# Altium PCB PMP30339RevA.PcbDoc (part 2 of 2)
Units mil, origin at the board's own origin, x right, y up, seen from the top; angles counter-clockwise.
Board outline 3000 x 2600 mil, 4 copper layers (Top Layer, Signal Layer 1, Signal Layer 2, Bottom Layer), stack 61.2 mil thick; 113 components, 43 nets, 222 pads, 187 vias.
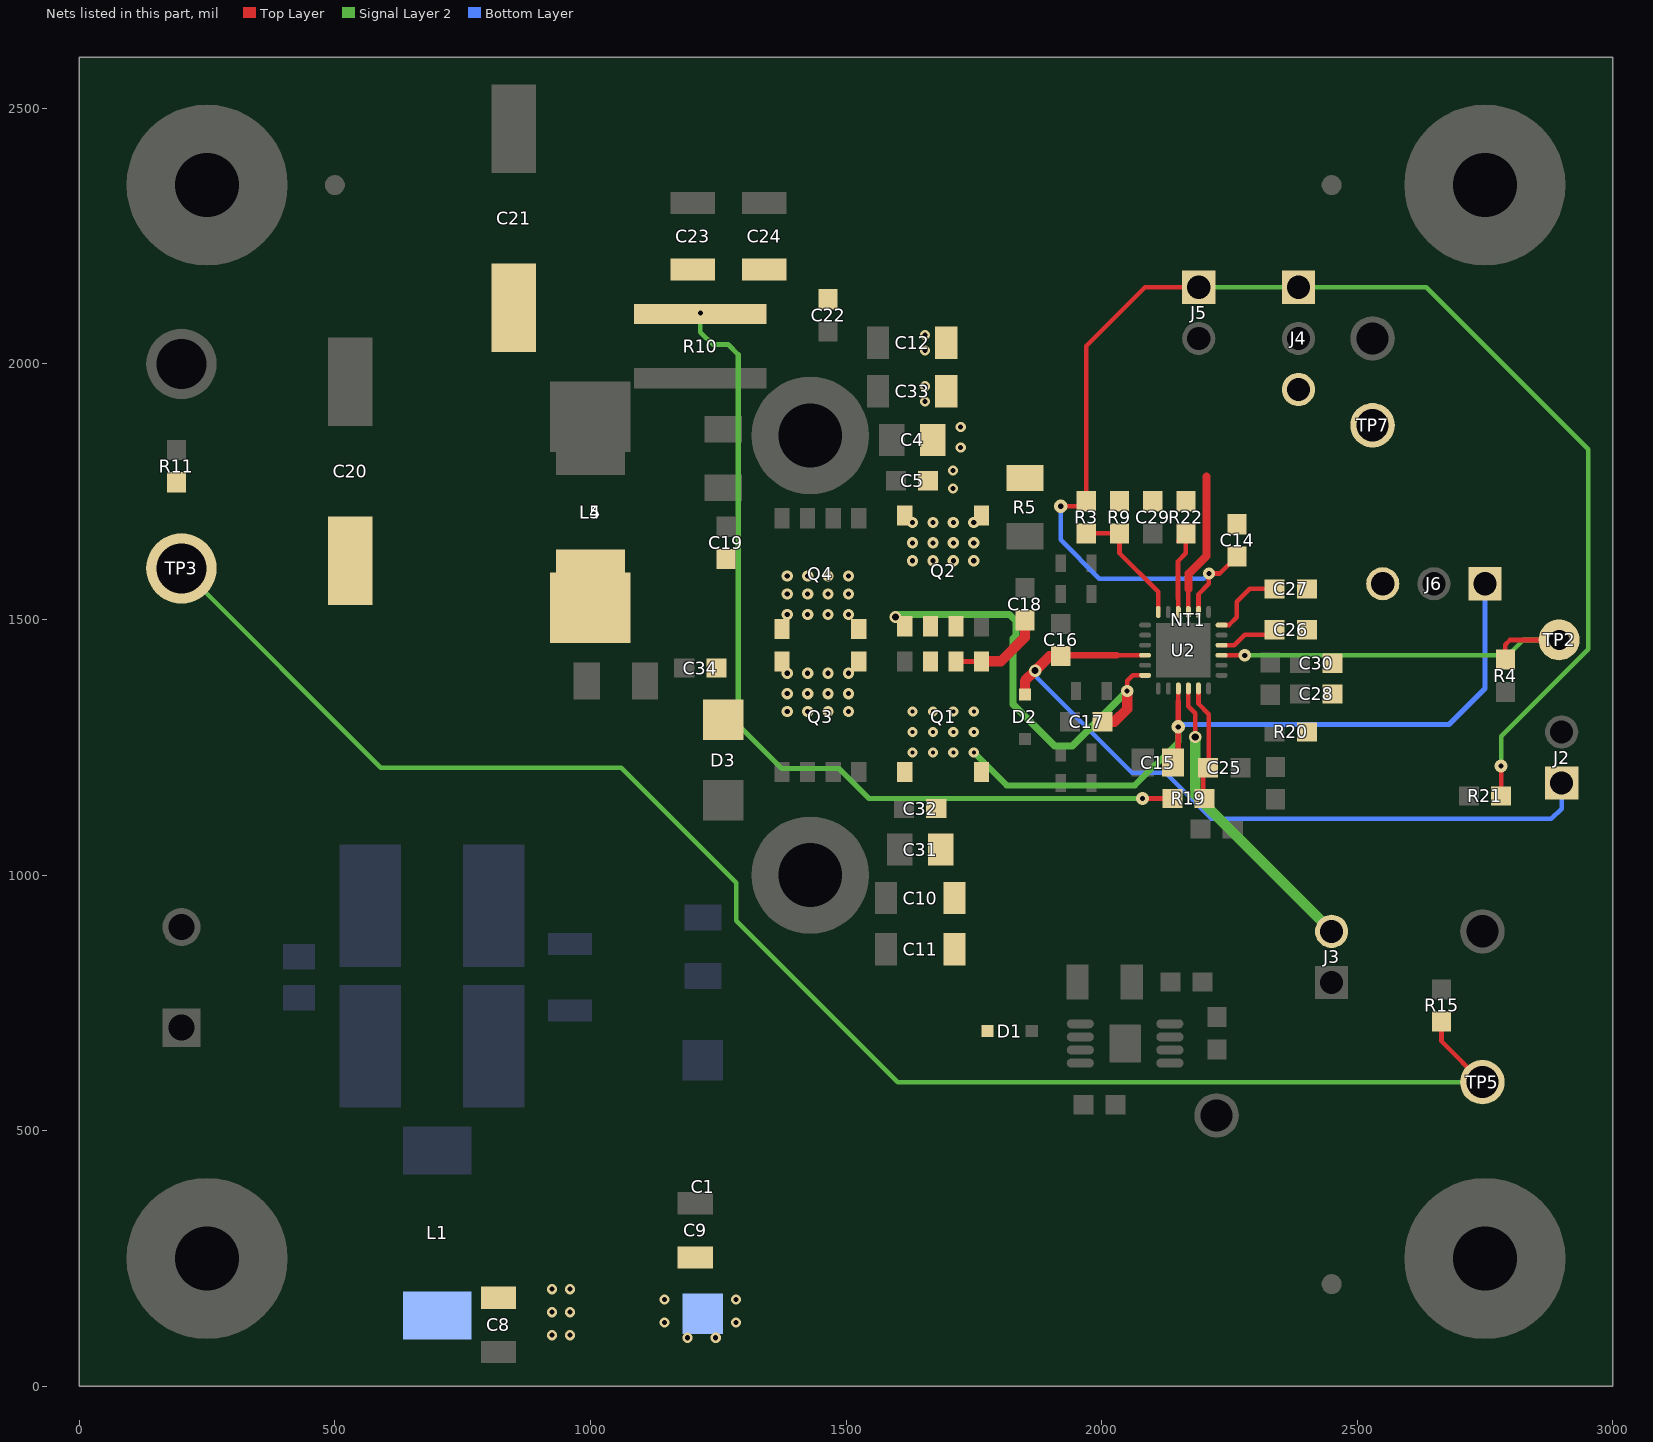
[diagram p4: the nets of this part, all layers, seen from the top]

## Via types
v1: diameter 20, hole 10, Top Layer to Bottom Layer, tented both sides, 54 vias
v2: diameter 20, hole 10, Top Layer to Bottom Layer, 49 vias
v3: diameter 22, hole 10, Top Layer to Bottom Layer, 36 vias
v4: diameter 20, hole 8, Top Layer to Bottom Layer, 12 vias
v5: diameter 18, hole 8, Top Layer to Bottom Layer, 10 vias
v6: diameter 24, hole 10, Top Layer to Bottom Layer, tented both sides, 7 vias
v7: diameter 26, hole 10, Top Layer to Bottom Layer, tented both sides, 6 vias
v8: diameter 24, hole 14, Top Layer to Bottom Layer, 5 vias
v9: diameter 26, hole 10, Top Layer to Bottom Layer, 4 vias
v10: diameter 24, hole 14, Top Layer to Bottom Layer, tented both sides, 2 vias
v11: diameter 30, hole 20, Top Layer to Bottom Layer, 1 vias
v12: diameter 22, hole 10, Top Layer to Bottom Layer, tented both sides, 1 vias

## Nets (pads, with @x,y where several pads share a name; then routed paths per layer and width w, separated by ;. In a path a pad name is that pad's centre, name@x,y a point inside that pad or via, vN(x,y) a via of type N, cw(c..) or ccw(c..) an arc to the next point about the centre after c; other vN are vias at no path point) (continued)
OSC: R3.2 R9.1 U2.6 | length 250.1
  Top Layer w9: R3.2@1970,1668.5 R9.1@2035,1668.5 2035,1630 2110.79,1554.21 U2.6@2110.79,1514.8
PG: R4.2 TP2.1 U2.21 | length 815.8
  Top Layer w9: U2.21@2234.8,1430.16 2269.84,1430.16 2270,1430 v6(2280,1430) ; R4.2@2790,1421.5 2790,1451.02 2798.98,1460 TP2.1@2895,1460
  Signal Layer 2 w9: v6(2280,1430) 2795,1430 2825,1460 TP2.1@2895,1460 ; TP2.1@2895.01,1430.11 TP2.1@2899.82,1430.12
RES: C27.1 U2.24 | length 150.6
  Top Layer w9: U2.24@2234.8,1489.21 2249.21,1489.21 2264.63,1504.63 2264.63,1534.63 2290,1560 C27.1@2338.5,1560
RT: R22.2 U2.4 | length 186.4
  Top Layer w9: U2.4@2150.16,1514.8 2150.16,1540 ; 2150.16,1545.16 2150.16,1540 ; R22.2@2150.16,1653.5 R22.2@2165,1668.35 2165,1629.66 2149.47,1614.13 2149.47,1540.69 2150.16,1540
SGND: C14.1 C26.2 C27.2 C28.2 C29.2 C30.2 J4.3 J6.3 NT1.1 R9.2 R20.1 R22.1 TP7.1 U2.3 | length 280.2
  Top Layer w9: U2.3@2169.84,1514.8 2169.84,1559.84
  Top Layer w16: 2169.84,1559.84 2169.84,1590 2170.58,1590 2205,1624.42 2205,1780
SS: C26.1 U2.22 | length 116.2
  Top Layer w9: U2.22@2234.8,1449.84 2259.84,1449.84 2280,1470 2328.5,1470 C26.1@2338.5,1480
SW: C17.2 C18.2 C19.1 C34.1 D3.1 L4.1 L5.1 Q1.1 Q1.2 Q1.3 Q2.1 Q2.2 Q2.3 Q3.5 Q3.6 Q4.5 Q4.6 U2.12 | length 1065.6
  Top Layer w9: v6(2050,1360) 2050,1380 2060.79,1390.79 U2.12@2085.2,1390.79
  Top Layer w10: Q1.2@1715,1418.17 Q1.1@1765,1418.17 ; C18.2@1840,1488.5 C18.2@1850,1498.5
  Top Layer w20: Q1.1@1765,1418.17 1803.17,1418.17 1850,1465 C18.2@1850,1498.5 ; C17.2@2001.5,1300 2024.98,1300 2050,1325.02 v6(2050,1360)
  Signal Layer 2 w14: v8(1596.89,1505) 1601.89,1510 1820,1510 1832.87,1497.13 1832.87,1468.45 1826.87,1462.45 1826.87,1334.06 1908.03,1252.91 1942.91,1252.91 v6(2050,1360)
  other v3: 1385,1320 1425,1320 1465,1320 1505,1320 1385,1355 1425,1355 1465,1355 1505,1355 1385,1395 1425,1395 1465,1395 1505,1395 1385,1510 1425,1510 1465,1510 1505,1510 1385,1550 1425,1550 1465,1550 1505,1550 1385,1585 1425,1585 1465,1585 1505,1585
VCC: C16.2 D2.2 J2.1 U2.10 | length 1497.2
  Top Layer w9: 2030.16,1430.16 U2.10@2085.2,1430.16
  Top Layer w12: C16.2@1920,1428.5 1921.65,1430.16 2030.16,1430.16
  Top Layer w20: D2.2@1850,1353.31 1850,1380 v10(1870,1400) 1898.5,1428.5 C16.2@1920,1428.5
  Bottom Layer w9: v10(1870,1400) 1870,1389.57 2059.57,1200 2125,1200 2215,1110 2880,1110 2900,1130 J2.1@2900,1180
VCCX: J3.2 U2.16 | length 626.7
  Top Layer w9: U2.16@2169.84,1365.2 2169.84,1330.16 2183,1317 ; v10@2183,1273 2180,1270 v10(2183.13,1270) 2183.13,1316.87
  Signal Layer 2 w9: J3.2@2430,910 J3.2@2450,890
  Signal Layer 2 w20: v10(2183.13,1270) 2183.13,1156.87 J3.2@2450,890
VDDA: C14.2 J4.1 J5.1 R3.1 R21.1 U2.2 | length 2811
  Top Layer w9: v7(1920,1721.5) 1960,1721.5 R3.1@1970,1731.5 1970,2035 2085,2150 J5.1@2190,2150 ; U2.2@2189.53,1514.8 2189.53,1549.53 2210,1570 v6(2210,1590) 2231.5,1590 C14.2@2265,1623.5 ; R21.1@2781.5,1155 v9(2781.5,1213.5)
  Signal Layer 2 w9: J5.1@2190,2150 J4.1@2385,2150 2635,2150 2952,1833 2952,1442 2781.5,1271.5 v9(2781.5,1213.5)
  Bottom Layer w9: v7(1920,1721.5) 1920,1655.75 1995.75,1580 2200,1580 v6(2210,1590)
VIN: C1.1 C4.1 C5.1 C8.1 C9.1 C10.1 C11.1 C12.1 C15.2 C31.1 C32.1 C33.1 D1.2 J6.1 L1.2 Q1.5 Q1.6 Q2.5 Q2.6 R5.2 U2.15 | length 1486.8
  Top Layer w9: 2150.16,1330.16 U2.15@2150.16,1365.2
  Top Layer w11: C15.2@2139.53,1220 2150,1230.47 v7(2150,1290) 2150.13,1330.13 ; 2150,1330 2150.16,1330.16 ; 2150.16,1339.59 2150.13,1330.13
  Signal Layer 2 w12: v4(1750,1240) 1814.51,1175.49 2065.25,1175.49 2150,1260.24 v7(2150,1290)
  Bottom Layer w10: v7(2150,1290) 2154.87,1294.87 2679.87,1294.87 2750,1365 J6.1@2750,1570
  other v2: 1190,95 1245,95 925,100 960,100 1145,125 1285,125 925,145 960,145 1145,170 1285,170 925,190 960,190 1709.28,1756.42 1709.28,1791.42 1724.28,1836.42 1724.28,1876.42 1654.28,1926.42 1654.28,1956.42 1654.28,2026.42 1654.28,2056.42
  other v3: 1630,1615 1670,1615 1710,1615 1750,1615 1630,1650 1670,1650 1710,1650 1750,1650 1630,1690 1670,1690 1710,1690 1750,1690
  other v4: 1630,1240 1670,1240 1710,1240 1630,1280 1670,1280 1710,1280 1750,1280 1630,1320 1670,1320 1710,1320 1750,1320
VO_IC: C25.1 R19.1 U2.17 | length 235.4
  Top Layer w9: U2.17@2189.53,1365.2 2189.53,1335.47 2210,1315 2210,1221.5 2198.5,1210 R19.1@2198.5,1142.99
VOUT: C20.1 C21.1 C22.1 C23.1 C24.1 R10.2 R11.2 R15.2 R19.2 TP3.1 TP5.1 | length 4919.8
  Top Layer w9: R15.2@2665,713.5 2665,675 TP5.1@2745,595
  Top Layer w10: v7@2090,1150 R19.2@2138.5,1150
  Signal Layer 2 w9: TP3.1@200,1600 590,1210 1060,1210 1285,985 1285,911.01 1601.01,595 TP5.1@2745,595 ; v2(1215,2099.94) 1215,2062.37 1240,2037.37 ; v7(2080,1150) v7@2090,1150
  Signal Layer 2 w10: 1240,2037.87 1269.5,2037.87 1289.31,2018.06 1289.31,1293.69 1374.44,1208.56 1486.44,1208.56 1545,1150 v7(2080,1150)
pads on no net: FID1.1 FID2.1 FID3.1 H1.1 H2.1 H3.1 H4.1 LBL1.0 U1.3 U1.7

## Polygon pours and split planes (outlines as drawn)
NetL4_2 on Top Layer "TopLayer-NetL4-2" (solid, remove dead copper, pour order 75): 920,1825 1080,1825 1080,1945 1345,1945 1345,1995 920,1995 920,1825
VOUT on Top Layer "Top Layer-VOUT" (solid, remove dead copper, pour order 70): 105,1490 105,1790 565,1790 590,1815 590,2250 1480,2250 1485,2250 1485,2100 1417.95,2100 1417.95,2075 865,2075 750,1960 750,1610 630,1490
VIN on Top Layer "Top Layer-VIN" (solid, remove dead copper, pour order 69): 1575,1536.85 1575,1725 1630,1725 1630,2080 1785,2080 1785,1985 1890,1880 1898.42,1871.58 1898.42,1739.52 1790.48,1739.52 1790,1740 1795.51,1734.49 1795.51,1536.85
VIN on Top Layer "Top Layer-VIN" (solid, remove dead copper, pour order 67): 1580,1358.66 1580,1365 1586.34,1365 1810,1365 1810,85 875,85 875,105 630,105 630,300 1580,300 1580,810 1650,810 1650,1160 1580,1160
SGND on Top Layer "Top Layer-SGND" (solid, remove dead copper, pour order 72): 2015,1690 2015,1990 2590,1990 2590,1150 2380,1150 2380,1490 2380,1590 2308.98,1590 2308.98,1635 2180,1635 2180,1690
GND on Top Layer "Top Layer-GND" (solid, pour order 76): 0.32,3.31 2997.53,0 2997.53,2596.7 -2.47,2596.7
SW on Top Layer "Top Layer-SW" (solid, remove dead copper, pour order 71): 1779.4,1385.2 1778.99,1440 1730,1440 1730,1520 1560,1520 1560,1645 1470,1645 1400,1645 920,1645 920,1455 1220,1455 1220,1420 1220,1259.51 1560,1259.51 1560,1385.2
LDO_OUT on Top Layer "Top Layer-LDO_Out" (solid, remove dead copper, pour order 74): 2180.96,810.71 2270.96,810.71 2270.96,700.71 2115.96,700.71 2115.96,725.71 2180.96,725.71 2180.96,810.71
LDO_IN on Top Layer "Top Layer-LDO_In" (solid, remove dead copper, pour order 73): 1850,675 1975,675 1975,830 1850,830 1850,675
NetC7_1 on Bottom Layer "Bottom Layer-NetC7-1" (solid, remove dead copper, pour order 102): 635,505 755,505 755,590 755,785 1005,785 1005,715 870,715 870,415 635,415
GND_IN on Bottom Layer "Bottom Layer-GND_IN" (solid, remove dead copper, pour order 108): 150,815 150,1060 300,1060 630,1060 630,815
+IN on Bottom Layer "Bottom Layer-+IN" (solid, remove dead copper, pour order 98): 150,785 630,785 630,660 630,545 150,545 150,785
VIN on Bottom Layer "Bottom Layer-Vin" (solid, remove dead copper, pour order 100): 630,240 630.39,240.39 1357.8,240.39 1357.8,27.2 1360,25 1360,0 630,0 630,240
GND on Bottom Layer "Bottom Layer-GND" (solid, pour order 110): 0,0 3000,0 3000,2600 0,2600
SW on Bottom Layer "BottomLayer-SW" (solid, remove dead copper, pour order 104): 1355,1645 1535,1645 1535,1260 1355,1260
VIN on Bottom Layer "BottomLayer-Vin" (solid, remove dead copper, pour order 106): 1600,1215 1785,1215 1785,1540 1785,2085 1630,2085 1630,1890 1600,1890 1600,1875 1600,1215
VIN on Signal Layer 1 "Signal Layer1-VIN" (solid, remove dead copper, pour order 78): 1630,2080 1785,2080 1785,1185 1560,1185 1560,1725 1630,1725
GND on Signal Layer 1 "Signal Layer1-GND" (solid, pour order 84): 0,0 3000,0 3000,2600 0,2600
SW on Signal Layer 1 "SignalLayer1-SW" (solid, remove dead copper, pour order 80): 1355,1645 1525,1645 1525,1260 1355,1260
VIN on Signal Layer 2 "Signal Layer2-VIN" (solid, remove dead copper, pour order 92): 1630,2065 1782.27,2065 1782.27,1600 1605,1600 1585,1600 1585,1725 1630,1725
VIN on Signal Layer 2 "Signal Layer2-VIN" (solid, remove dead copper, pour order 86): 1615,1335 1784.16,1335 1784.16,1200 1615,1200
GND on Signal Layer 2 "Signal Layer2-GND" (solid, pour order 96): 0,0 3000,0 3000,2600 0,2600
SW on Signal Layer 2 "SignalLayer2-SW" (solid, remove dead copper, pour order 94): 1355,1645 1525,1645 1525,1260 1355,1260

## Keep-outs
Keep-Out Layer:
  the board outline again, w7
  text ".Layer_Name" at 577,-858.49 h60

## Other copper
Top Layer:
  pour cut-out: 790,1945 920,1945 920,1775 1080,1775 1080,1945 1210,1945 1210,1650 1165,1650 920,1650 920,1445 1210,1445 1210,1415 1210,1245 1305,1245 1305,1195 1210,1195 1140,1195 1140,1315 1055,1315 1055,1340 1025,1340 1025,1415 865,1415 865,1475 790,1475
  pour cut-out: 0,0 625,0 625,300 1155,300 1155,995 1000,1150 0,1150
  text ".Layer_Name" at 577,-858.49 h60
Signal Layer 1:
  pour cut-out: 790,1945 1210,1945 1210,1475 790,1475
  pour cut-out: 0,0 1155,0 1155,730 1155,995 1000,1150 0,1150
  text ".layer_Name" at 577,-858.49 h40
Signal Layer 2:
  pour cut-out: 0,0 1155,0 1155,995 1000,1150 0,1150
  text ".layer_Name" at 577,-858.49 h40
Bottom Layer:
  pour cut-out: 0,0 625,0 625,250 1155,250 1155,995 1155,950 750,950 750,840 1155,840 1155,995 1000,1150 0,1150 0,1062.5 0,540 150,540 150,1062.5 637.5,1062.5 637.5,790 635,515 750,515 750,790 870,790 1010,790 1010,760 1010,710 870,710 870,540 870,415 625,415 625,540 0,540
  text ".Layer_Name" at 577,-858.49 h60

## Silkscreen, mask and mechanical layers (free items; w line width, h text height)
Top Overlay:
  region: 2400,139.99 2100,139.99 2100,39.99 2400,39.99
  text "-" at 40,1960 h80
  text "+" at 40,1560 h80
  text "-" at 175,935 h80
  text "Input" at 140,790 h72.83
  text "+" at 170,565 h80
  text ".PRJ_Number" at 1420,59.99 h60
  text ".PCB_Rev" at 1920,60 h60
  text "-" at 2030,60 h40
  text ".Layer_Name" at 577,-858.49 h60
Bottom Overlay:
  text ".Layer_Name" at 577,-858.49 h60
Top Paste:
  text ".Layer_Name" at 577,-858.49 h60
Bottom Paste:
  text ".Layer_Name" at 577,-858.49 h60
Top Solder:
  text ".Layer_Name" at 577,-858.49 h60
  text ".Layer_Name" at 577,-858.49 h60
Bottom Solder:
  text ".Layer_Name" at 577,-858.49 h60
Drill Guide:
  text ".Layer_Name" at 577,-858.49 h60
M1 Board Outline:
  the board outline again, w10
  text ".Layer_Name" at 577,-858.49 h60
M2 Board Dimensions:
  rectangle: 0,-275 125,-150
  rectangle: 125,-400 500,-275
  lines w7: 0,-275 1000,-275 ; 125,-400 125,-150 ; 250,-400 250,-150 ; 500,-400 500,-150 ; 750,-400 750,-150 ; 0,-400 1000,-400 1000,-150 0,-150 0,-400
  text ".Layer_Name" at 577,-858.49 h60
M3 3D STEP Top:
  text ".Layer_Name" at 577,-858.49 h60
M4 3D STEP Bottom:
  text ".Layer_Name" at 577,-858.49 h60
M5 Assembly Top:
  lines w10: -292,-930.17 6308,-930.17 ; -292,-726.83 6310,-726.83 ; -292,-523.5 -292,-1133.5 3713,-1133.5 6310,-1133.5 6310,-523.5 -291.5,-523.5 -291.5,-1133.5 1284,-1133.5 ; 2173,-1133.5 2173,-523.5 ; 3440,-726.83 3440,-523.5 ; 4280,-726.83 4280,-523.5 ; 4902,-1140 4902,-937.17
  text "COMPONENTS MARKED 'DNP' SHOULD NOT BE POPULATED." at 1153.5,-318.5 h40
  text "ASSEMBLY VARIANT:" at 1153,-434 h40
  text ".VariantName" at 2189,-434 h40
  text "PCB VIEWED FROM TOP SIDE" at -228.5,-655.67 h60
  text "BOARD #:" at 2248,-655.67 h60
  text ".PRJ_Number" at 2793.5,-655.67 h60
  text "REV:" at 3638,-655.67 h60
  text ".PCB_Rev" at 3929.5,-655.67 h60
  text "SVN REV:" at 4476,-655.67 h60
  text ".VersionControl_RevNumber" at 4982,-655.67 h60
  text "TID #:" at 2248,-859 h60
  text ".TID" at 2793.5,-859 h60
  text "PLOT NAME =" at -228.5,-1064.34 h60
  text ".plot_File_Name" at 577,-1064.34 h60
  text "GENERATED    :" at 2250,-1064.34 h60
  text ".Print_Date" at 3119.5,-1064.34 h60
  text ".Print_Time" at 3848.5,-1064.34 h60
  text "TEXAS INSTRUMENTS" at 5113,-1064.34 h60
M6 Assembly Bottom:
  lines w10: -292.5,-727.33 6309.5,-727.33 ; -290.5,-930.67 6309.5,-930.67 ; 1115.5,-1140.5 1115.5,-937.67 ; 1737.5,-727.33 1737.5,-524 ; 2577.5,-727.33 2577.5,-524 ; 3844.5,-1134 3844.5,-524 ; 4733.5,-1134 6309,-1134 6309,-524 -292.5,-524 -292.5,-1134 2304.5,-1134 6309.5,-1134 6309.5,-524
  text "COMPONENTS MARKED 'DNP' SHOULD NOT BE POPULATED." at 6102,-318 h40
  text ".VariantName" at 5058,-434 h40
  text "ASSEMBLY VARIANT:" at 6097,-434 h40
  text ".VersionControl_RevNumber" at 1035.5,-656.17 h60
  text "SVN REV:" at 1541.5,-656.17 h60
  text ".PCB_Rev" at 2088,-656.17 h60
  text "REV:" at 2379.5,-656.17 h60
  text ".PRJ_Number" at 3224,-656.17 h60
  text "BOARD #:" at 3769.5,-656.17 h60
  text "PCB VIEWED FROM BOTTOM SIDE" at 6246,-656.17 h60
  text ".TID" at 3224,-859.5 h60
  text "TID #:" at 3769.5,-859.5 h60
  text "TEXAS INSTRUMENTS" at 904.5,-1064.84 h60
  text ".Print_Time" at 2169,-1064.84 h60
  text ".Print_Date" at 2898,-1064.84 h60
  text "GENERATED    :" at 3767.5,-1064.84 h60
  text ".plot_File_Name" at 5440.5,-1064.84 h60
  text "PLOT NAME =" at 6246,-1064.84 h60
M9 Title Sheet:
  drawing of 57 lines, arcs and shapes, not listed
  text "1" at 739.84,8036.5 h70
  text "2" at 3235.5,8036.5 h70
  text "3" at 5724.84,8036.5 h70
  text "4" at 8231.51,8036.5 h70
  text "5" at 10730.5,8036.5 h70
  text "6" at 13235.5,8036.5 h70
  text "A" at -416.5,6893.5 h70
  text "A" at 14383.5,6893.5 h70
  text "B" at -416.5,4513.5 h70
  text "B" at 14383.5,4513.5 h70
  text "C" at -416.5,2138.5 h70
  text "C" at 14383.5,2138.5 h70
  text "PROJECT TITLE:" at 11343.5,277.5 h45
  text ".PRJ_Title" at 11393.5,144.17 h70
  text "DESIGNED FOR:" at 11343.5,-23.5 h45
  text ".PRJ_Customer" at 11393.5,-163.5 h70
  text "D" at -416.5,-231.5 h70
  text "D" at 14383.5,-231.5 h70
  text "FILE NAME:" at 11343.5,-323.5 h45
  text ".PCB_File_Name_No_Path" at 11393.5,-443.5 h70
  text "Texas Instruments (TI) and/or its licensors do not warrant the accuracy or completeness of this specification" at 6374,-605.34 h45
  text "ENGINEER:" at 11343.5,-613.5 h45
  text "LAYOUT BY:" at 12848.5,-613.5 h45
  text "or any information contained therein. TI and/or its licensors do not warrant that this design will meet" at 6329.01,-718 h45
  text ".PRJ_Engineer" at 11393.5,-768.49 h70
  text ".PCB_Layout" at 12899,-768.49 h70
  text "the specifications, will be suitable for your application or fit for any particular purpose, or will operate in" at 6329.01,-830.67 h45
  text ".Layer_Name" at 577,-858.49 h60
  text "ALTIUM DESIGNER VERSION:" at 12848.5,-923.5 h45
  text "an implementation. TI and/or its licensors do not warrant that the design is production worthy. You should" at 6329.01,-943.33 h45
  text "completely validate and test your design implementation to confirm the system functionality for your application." at 6374,-1056 h45
  text ".print_Scale" at 11393.5,-1056.83 h70
  text ".Application_BuildNumber" at 12899,-1056.83 h70
  text "1" at 739.84,-1263.5 h70
  text "2" at 3235.5,-1263.5 h70
  text "3" at 5724.84,-1263.5 h70
  text "4" at 8231.51,-1263.5 h70
  text "5" at 10730.5,-1263.5 h70
  text "6" at 13235.5,-1263.5 h70
M10 Fab Notes:
  drawing of 185 lines, arcs and shapes, not listed
  text "DESIGN INFORMATION" at 12381.02,5910 h60
  text "MIN. TRACK WIDTH:" at 11736.46,5730 h60
  text "8" at 12832.7,5730 h60
  text "MIL" at 12987.46,5730 h60
  text "MIN. CLEARANCE:" at 11736.46,5598 h60
  text "0.2" at 12772.7,5598 h60
  text "mm" at 12987.46,5598 h60
  text "MIN. VIA PAD SIZE:" at 11736.46,5466 h60
  text "24" at 12802.71,5466 h60
  text "MIL" at 12987.46,5466 h60
  text "0.152mm (6MIL)" at 12431.46,5324.29 h60
  text "MINIMUM ANNULAR RING" at 11407.23,5320 h60
  text "EXTERNAL" at 13139.46,5320 h60
  text "PER" at 11607.23,5202 h60
  text "IPC-D-275 CLASS 2 LEVEL C" at 11827.23,5202 h60
  text "MIL, HOLES" at 13315.46,5089.71 h60
  text "+/-" at 12923,5089 h60
  text "+/-" at 13777,5089 h60
  text "REGISTRATION TOLERANCES:" at 11407.23,5084 h60
  text "METAL" at 12607,5084 h60
  text "5" at 13183.2,5084 h60
  text "3" at 14016.2,5084 h60
  text "MIL" at 14132.46,5084 h60
  text "MATERIAL:" at 11332.46,4874.54 h60
  text "FR-4 High Tg" at 12318.9,4734.21 h60
  text "FR-408" at 11753.46,4725.64 h60
  text "X" at 12165.46,4725.64 h60
  text "OTHER" at 13241.46,4725.64 h60
  text "62 MIL (1.6mm) +/-10%" at 12073.56,4562.92 h60
  text "THICKNESS:" at 11407.23,4558.64 h60
  text "X" at 11945.4,4558.64 h60
  text "OTHER" at 13358.46,4558.64 h60
  text "TOLERANCE:" at 11407.23,4400.64 h60
  text "X" at 12246.53,4400.64 h60
  text "ANSI IPC-6012 TYPE 3 CLASS 2" at 12433.48,4400.64 h60
  text "OTHER +/-" at 12433.46,4244.64 h60
  text "BOW & TWIST:" at 11407.23,4087.64 h60
  text "X" at 12246.53,4087.64 h60
  text "ANSI IPC-6012 TYPE 3 CLASS 2" at 12433.48,4087.64 h60
  text "OTHER +/-" at 12433.46,3929.13 h60
  text "DRILLING:" at 11332.46,3790.64 h60
  text "REFERENCE:" at 11407.23,3673.64 h60
  text "X" at 12055.46,3673.64 h60
  text "AS SHOWN" at 12242.46,3673.64 h60
  text "X" at 12956.46,3673.64 h60
  text "NC_DRILL FILES" at 13093.46,3673.64 h60
  text "PTH MIN COPPER THICKNESS:" at 11407.23,3515.64 h60
  text "X" at 12757.46,3515.64 h60
  text "1MIL" at 12894.46,3515.64 h60
  text "OTHER" at 13391.46,3515.64 h60
  text "BOARD FINISH:" at 11332.46,3356.64 h60
  text "SILKSCREEN:" at 11487.68,3238.64 h60
  text "X" at 12436.46,3238.64 h60
  text "TOP" at 12562.46,3238.64 h60
  text "X" at 12946.46,3238.64 h60
  text "BOTTOM" at 13073.46,3238.64 h60
  text "SILKSCREEN COLOR:" at 11487.68,3071.64 h60
  text "X" at 12435.42,3071.64 h60
  text "WHITE" at 12562.46,3071.64 h60
  text "OTHER" at 13073.46,3071.64 h60
  text "SOLDER RESIST COLOR:" at 11487.68,2901.64 h60
  text "X" at 12055.42,2742.44 h60
  text "GREEN" at 12182.46,2742.44 h60
  text "BLUE" at 12773.46,2742.44 h60
  text "OTHER" at 13311.46,2742.44 h60
  text "IMMERSION GOLD (ENIG)" at 12393.46,2553.92 h60
  text "ENEPIG" at 13731,2550.64 h60
  text "SURFACE FINISH:" at 11332.46,2549.64 h60
  text "X" at 12206.51,2549.64 h60
  text "IMM. TIN/SILVER OR EQUIV" at 11662,2392.64 h60
  text "OTHER" at 13093.46,2392.64 h60
  text "ARRAY/PANEL:" at 11332.46,2213.64 h60
  text "CUT AND TRIM PER MECH LAYER 1" at 12393.46,2209.35 h60
  text "X" at 12205,2205 h60
  text "N.C. ROUTE" at 12393.46,2057.64 h60
  text "V. SCORE" at 13259.46,2057.64 h60
  text "CERTIFICATION:" at 11332.46,1920.64 h60
  text "MATERIALS AND WORKMANSHIP FOR ALL PCBS" at 12057.46,1920.64 h60
  text "TO MEET OR EXCEED THE REQUIREMENTS OF:" at 12057.46,1822.64 h60
  text "X" at 11683.96,1686.13 h60
  text "ANSI IPC-A-600F CLASS ->" at 11822.96,1686.13 h60
  text "X" at 13462.02,1686.13 h60
  text "2" at 13580.96,1686.14 h60
  text "1" at 13265.96,1684.64 h60
  text "3" at 13934.96,1684.64 h60
  text "X" at 11686.02,1526.64 h60
  text "UL 94V-0" at 11822.96,1526.64 h60
  text "X" at 12498.02,1526.64 h60
  text "RoHS" at 12634.96,1526.64 h60
  text "OTHER" at 13279.36,1526.64 h60
  text "PER ORDER" at 13676.42,1526.64 h60
  text "ADDITIONAL REQUIREMENTS:" at 11332.46,1385.64 h60
  text "MICROSECTION:" at 11407.23,1270.64 h60
  text "YES" at 12312.96,1270.64 h60
  text "REQUIRED" at 13174.46,1114.49 h60
  text "BARE BOARD ELEC. TEST:" at 11407.23,1111.64 h60
  text "NONE" at 12712.96,1111.64 h60
  text "X" at 13047.46,1111.64 h60
  text "PER ORDER" at 13766.46,1111.64 h60
  text "MANUFACTURER'S UL:" at 11407.23,954.64 h60
  text "RAIL" at 12572.96,950.35 h60
  text "METAL" at 13064.77,950.35 h60
  text "X" at 13440,950 h60
  text "SILK" at 13576.46,950.35 h60
  text ".Layer_Name" at 577,-858.49 h60
M11 Gerber Information:
  lines w10: -292,-930.17 6308,-930.17 ; -292,-726.83 6310,-726.83 ; -292,-523.5 -292,-1133.5 3713,-1133.5 6310,-1133.5 6310,-523.5 -291.5,-523.5 -291.5,-1133.5 1284,-1133.5 ; 2173,-1133.5 2173,-523.5 ; 3440,-726.83 3440,-523.5 ; 4280,-726.83 4280,-523.5 ; 4902,-1140 4902,-937.17
  text "ALL ARTWORK VIEWED FROM TOP SIDE" at -228.5,-655.67 h60
  text "BOARD #:" at 2248,-655.67 h60
  text ".PRJ_Number" at 2793.5,-655.67 h60
  text "REV:" at 3638,-655.67 h60
  text ".PCB_Rev" at 3929.5,-655.67 h60
  text "SVN REV:" at 4476,-655.67 h60
  text ".VersionControl_RevNumber" at 4982,-655.67 h60
  text "LAYER NAME =" at -228.5,-858.49 h60
  text "TID #:" at 2248,-859 h60
  text ".TID" at 2793.5,-859 h60
  text "PLOT NAME =" at -228.5,-1064.34 h60
  text ".plot_File_Name" at 577,-1064.34 h60
  text "GENERATED    :" at 2250,-1064.34 h60
  text ".Print_Date" at 3119.5,-1064.34 h60
  text ".Print_Time" at 3848.5,-1064.34 h60
  text "TEXAS INSTRUMENTS" at 5113,-1064.34 h60
M12 Stackup:
  drawing of 295 lines, arcs and shapes, not listed
  text "Layer" at 9777.84,7870 h40
  text "Name" at 10057.78,7870 h40
  text "Material" at 10690.95,7870 h40
  text "Thickness" at 11270.79,7870 h40
  text "Constant" at 11710.68,7870 h40
  text "Board Layer Stack" at 12097.26,7870 h40
  text "1" at 9777.84,7790 h40
  text "Top Overlay" at 10057.78,7790 h40
  text "2" at 9777.84,7710 h40
  text "Top Solder" at 10057.78,7710 h40
  text "Solder Resist" at 10690.95,7710 h40
  text "0.40mil" at 11270.79,7710 h40
  text "3.5" at 11710.68,7710 h40
  text "3" at 9777.84,7630 h40
  text "Top Layer" at 10057.78,7630 h40
  text "Copper" at 10690.95,7630 h40
  text "2.80mil" at 11270.79,7630 h40
  text "4" at 9777.84,7550 h40
  text "Dielectric1" at 10057.78,7550 h40
  text "FR-4" at 10690.95,7550 h40
  text "16.00mil" at 11270.79,7550 h40
  text "4.8" at 11710.68,7550 h40
  text "5" at 9777.84,7470 h40
  text "Signal Layer 1" at 10057.78,7470 h40
  text "Copper" at 10690.95,7470 h40
  text "2.80mil" at 11270.79,7470 h40
  text "6" at 9777.84,7390 h40
  text "Dielectric 3" at 10057.78,7390 h40
  text "18.00mil" at 11270.79,7390 h40
  text "4.2" at 11710.68,7390 h40
  text "7" at 9777.84,7310 h40
  text "Signal Layer 2" at 10057.78,7310 h40
  text "Copper" at 10690.95,7310 h40
  text "2.80mil" at 11270.79,7310 h40
  text "8" at 9777.84,7230 h40
  text "Dielectric 2" at 10057.78,7230 h40
  text "FR-4" at 10690.95,7230 h40
  text "16.00mil" at 11270.79,7230 h40
  text "4.2" at 11710.68,7230 h40
  text "9" at 9777.84,7150 h40
  text "Bottom Layer" at 10057.78,7150 h40
  text "Copper" at 10690.95,7150 h40
  text "2.80mil" at 11270.79,7150 h40
  text "10" at 9777.84,7070 h40
  text "Bottom Solder" at 10057.78,7070 h40
  text "Solder Resist" at 10690.95,7070 h40
  text "0.40mil" at 11270.79,7070 h40
  text "3.5" at 11710.68,7070 h40
  text "11" at 9777.84,6990 h40
  text "Bottom Overlay" at 10057.78,6990 h40
  text ".Layer_Name" at 577,-858.49 h60
M13 Component Bodies Top:
  text ".Layer_Name" at 577,-858.49 h60
M14 Component Bodies Bottom:
  text ".Layer_Name" at 577,-858.49 h60
M15 Courtyards Top:
  text ".Layer_Name" at 577,-858.49 h60
M16 Courtyards Bottom:
  text ".Layer_Name" at 577,-858.49 h60
Drill Drawing:
  circle w10: c3658.77,671.76 r11.03
  circle w10: c3658.77,671.76 r18.39
  lines w10: 3640.38,497.08 3649.58,497.08 3658.77,487.88 3667.97,497.08 3677.16,497.08 3667.97,506.27 3677.16,515.47 3667.97,515.47 3658.77,524.66 3649.58,515.47 3640.38,515.47 3649.58,506.27 3640.38,497.08 ; 3640.38,579.82 3649.58,579.82 3658.77,570.63 3667.97,579.82 3677.16,579.82 3667.97,589.02 3677.16,598.21 3667.97,598.21 3658.77,607.4 3649.58,598.21 3640.38,598.21 3649.58,589.02 3640.38,579.82 ; 3640.38,855.64 3677.16,855.64 3658.77,818.86 3640.38,855.64 ; 3640.38,901.61 3658.77,910.8 3677.16,901.61 3667.97,920 3677.16,938.38 3658.77,929.19 3640.38,938.38 3649.58,920 3640.38,901.61 ; 3640.38,984.35 3677.16,984.35 3677.16,1021.13 3640.38,1021.13 3640.38,984.35 ; 3640.38,1067.1 3677.16,1067.1 3677.16,1103.87 3640.38,1103.87 3640.38,1067.1 ; 3640.38,1186.62 3677.16,1186.62 3658.77,1149.84 3640.38,1186.62 ; 3640.38,1232.59 3640.38,1241.78 3649.58,1250.98 3640.38,1260.17 3640.38,1269.36 3649.58,1269.36 3658.77,1260.17 3667.97,1269.36 3677.16,1269.36 3677.16,1260.17 3667.97,1250.98 3677.16,1241.78 3677.16,1232.59 3667.97,1232.59 3658.77,1241.78 3649.58,1232.59 3640.38,1232.59 ; 3640.38,1324.53 3649.58,1324.53 3649.58,1315.33 3667.97,1315.33 3667.97,1324.53 3677.16,1324.53 3677.16,1342.92 3667.97,1342.92 3667.97,1352.11 3649.58,1352.11 3649.58,1342.92 3640.38,1342.92 3640.38,1324.53 ; 3647.74,500.76 3653.26,500.76 3658.77,495.24 3664.29,500.76 3669.8,500.76 3664.29,506.27 3669.8,511.79 3664.29,511.79 3658.77,517.3 3653.26,511.79 3647.74,511.79 3653.26,506.27 3647.74,500.76 ; 3647.74,848.28 3669.8,848.28 3658.77,826.22 3647.74,848.28 ; 3647.74,908.96 3658.77,914.48 3669.8,908.96 3664.29,920 3669.8,931.03 3658.77,925.51 3647.74,931.03 3653.26,920 3647.74,908.96 ; 3647.74,991.71 3669.8,991.71 3669.8,1013.77 3647.74,1013.77 3647.74,991.71 ; 3647.74,1239.94 3647.74,1245.46 3653.26,1250.98 3647.74,1256.49 3647.74,1262.01 3653.26,1262.01 3658.77,1256.49 3664.29,1262.01 3669.8,1262.01 3669.8,1256.49 3664.29,1250.98 3669.8,1245.46 3669.8,1239.94 3664.29,1239.94 3658.77,1245.46 3653.26,1239.94 3647.74,1239.94 ; 3647.74,1328.2 3653.26,1328.2 3653.26,1322.69 3664.29,1322.69 3664.29,1328.2 3669.8,1328.2 3669.8,1339.24 3664.29,1339.24 3664.29,1344.75 3653.26,1344.75 3653.26,1339.24 3647.74,1339.24 3647.74,1328.2
  lines w12: 3606,463.06 4924.18,463.06 ; 3606,1373.26 4924.18,1373.26 ; 3831.14,380.32 3831.14,1456 ; 4052.39,380.32 4052.39,1456 ; 4476.64,380.32 4476.64,1456 ; 4649.32,380.32 4649.32,1456 ; 3606,380.32 4924.18,380.32 4924.18,1456 3606,1456 3606,380.32
  text "Symbol" at 3655.65,1398.08 h48
  text "Quantity" at 3855.97,1398.08 h48
  text "Finished Hole Size" at 4077.22,1398.08 h48
  text "Plated" at 4501.47,1398.08 h48
  text "Hole Type" at 4674.14,1398.08 h48
  text "22" at 3855.97,1315.33 h40
  text "8.00mil (0.203mm)" at 4077.22,1315.33 h40
  text "PTH" at 4501.47,1315.33 h40
  text "Round" at 4674.14,1315.33 h40
  text "157" at 3855.97,1232.59 h40
  text "10.00mil (0.254mm)" at 4077.22,1232.59 h40
  text "PTH" at 4501.47,1232.59 h40
  text "Round" at 4674.14,1232.59 h40
  text "7" at 3855.97,1149.84 h40
  text "14.00mil (0.356mm)" at 4077.22,1149.84 h40
  text "PTH" at 4501.47,1149.84 h40
  text "Round" at 4674.14,1149.84 h40
  text "1" at 3855.97,1067.1 h40
  text "20.00mil (0.508mm)" at 4077.22,1067.1 h40
  text "PTH" at 4501.47,1067.1 h40
  text "Round" at 4674.14,1067.1 h40
  text "1" at 3855.97,984.35 h40
  text "40.00mil (1.016mm)" at 4077.22,984.35 h40
  text "PTH" at 4501.47,984.35 h40
  text "Round" at 4674.14,984.35 h40
  text "12" at 3855.97,901.61 h40
  text "45.28mil (1.150mm)" at 4077.22,901.61 h40
  text "PTH" at 4501.47,901.61 h40
  text "Round" at 4674.14,901.61 h40
  text "2" at 3855.97,818.86 h40
  text "51.18mil (1.300mm)" at 4077.22,818.86 h40
  text "PTH" at 4501.47,818.86 h40
  text "Round" at 4674.14,818.86 h40
  text "5" at 3855.97,736.12 h40
  text "63.00mil (1.600mm)" at 4077.22,736.12 h40
  text "PTH" at 4501.47,736.12 h40
  text "Round" at 4674.14,736.12 h40
  text "B" at 3636.52,726.12 h36.78
  text "2" at 3855.97,653.37 h40
  text "98.43mil (2.500mm)" at 4077.22,653.37 h40
  text "PTH" at 4501.47,653.37 h40
  text "Round" at 4674.14,653.37 h40
  text "2" at 3855.97,570.63 h40
  text "125.00mil (3.175mm)" at 4077.22,570.63 h40
  text "PTH" at 4501.47,570.63 h40
  text "Round" at 4674.14,570.63 h40
  text "4" at 3855.97,487.88 h40
  text "125.98mil (3.200mm)" at 4077.22,487.88 h40
  text "PTH" at 4501.47,487.88 h40
  text "Round" at 4674.14,487.88 h40
  text "215 Total" at 3855.97,405.14 h40
  text ".Layer_Name" at 577,-858.49 h60

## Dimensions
0,-400 to 1000,-400 on M2 Board Dimensions
0,300 to 0,2600 on M2 Board Dimensions
0,300 to 3000,0 on M2 Board Dimensions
